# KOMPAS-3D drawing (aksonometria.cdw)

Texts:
  Текст на чертеже
  Размерные надписи
  Шероховатость
  Линия-выноска #1
  Линия-выноска #2
  Линия-выноска #3
  Отклонения формы и база
  Заголовок таблицы
  Ячейка таблицы
  Стрелка вида
  Обозначение изменения
  Фигурная скобка
  Номер узла
  Марка координационной оси
  VRCB
  Выносная надпись
  Обозначение узла
  Марка/позиционное обозначение с линией-выноской
  Марка/позиционное обозначение на линии
  Марка/позиционное обозначение без линии-выноски
Dimensions and other numbers on the sheet: 7; 16; 43; 45; 80; 12; 40; 50; 4; 20; 1:1; 1; 0; 2; 3; 5; 6; 8; 9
